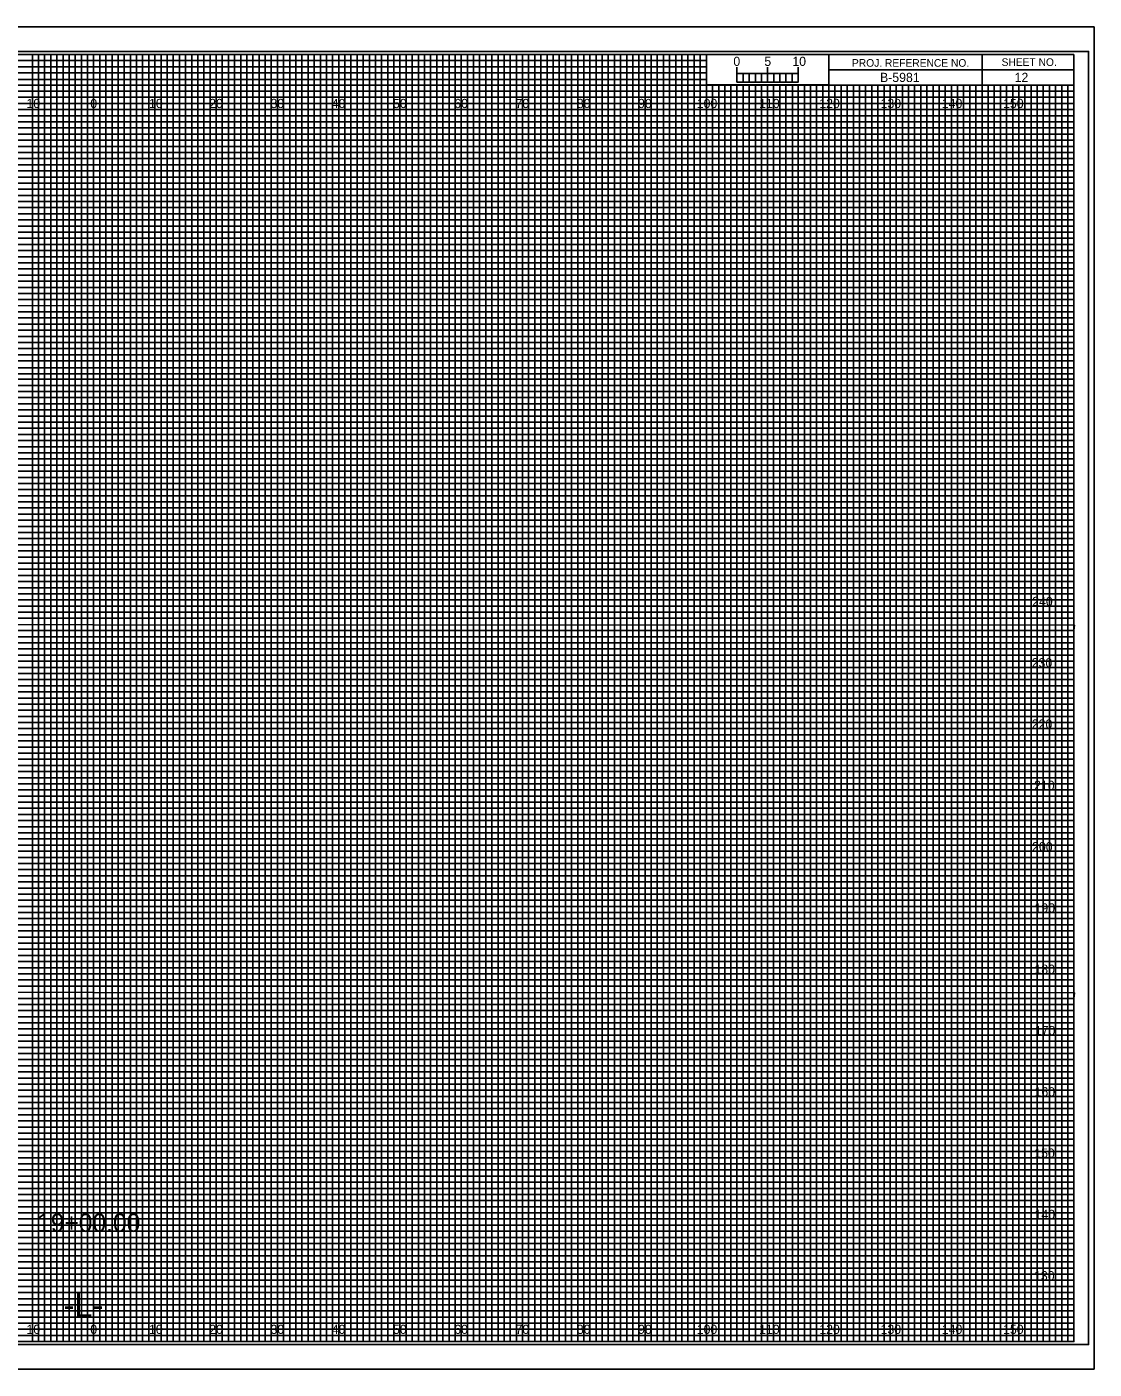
# Model space of a CAD drawing. Extents: x -13 to 323, y -5 to 4174.
# Drawn here: x 149.1 to 323.3, y 1315.5 to 1534.5 of the extents above; entities that cross this region are included whole.
import ezdxf

# ---------------------------------------------------------------- set-up
doc = ezdxf.new("R2010")
doc.units = 0
for name, color, linetype in [('Exist Cross Section Cell', 7, 'Continuous'), ('Exist XS Center Line Elevation Label', 7, 'Continuous'), ('Exist XS Ground Line', 7, 'Continuous'), ('Prop CMT Concrete Structures', 7, 'Continuous'), ('Prop CMT Guardrail Graphics', 7, 'Continuous'), ('Prop CMT Pvmt Course 1', 7, 'Continuous'), ('Prop CMT Pvmt Course 2', 7, 'Continuous'), ('Prop CMT Pvmt Course 3', 7, 'Continuous'), ('Prop CMT Pvmt Surface', 7, 'Continuous'), ('Prop CMT Shld Paved Course 1', 7, 'Continuous'), ('Prop CMT Shld Paved Course 2', 7, 'Continuous'), ('Prop CMT Shld Paved Course 3', 7, 'Continuous'), ('Prop CMT Subgrade Earthwork', 7, 'Continuous'), ('Prop XS Ditch Standard Text', 7, 'Continuous'), ('Prop XS SE Text', 7, 'Continuous'), ('Prop XS Side Slope Text', 7, 'Continuous'), ('Scratch_Level_0', 7, 'Continuous')]:
    doc.layers.add(name, color=color, linetype=linetype)

msp = doc.modelspace()

# ---------------------------------------------------------------- linework, layer by layer
at = {"layer": 'Exist XS Center Line Elevation Label'}
for points in [[(145, 1320), (155, 1320), (155, 1530), (165, 1530), (165, 1320), (175, 1320), (175, 1530), (185, 1530), (185, 1320), (195, 1320), (195, 1530), (205, 1530), (205, 1320), (215, 1320), (215, 1530), (225, 1530), (225, 1320), (235, 1320), (235, 1530), (245, 1530), (245, 1320), (255, 1320), (255, 1530), (259.93, 1530), (260, 1530), (260, 1525), (264.99, 1525), (264.99, 1320), (275, 1320), (275, 1525), (285, 1525), (285, 1320), (295, 1320), (295, 1525), (305, 1525), (305, 1320), (315, 1320), (315, 1525)], [(0, 1525), (275, 1525)], [(0, 1505), (320, 1505), (320, 1515), (0, 1515)], [(0, 1485), (320, 1485), (320, 1495), (0, 1495)], [(0, 1465), (320, 1465), (320, 1475), (0, 1475)], [(0, 1445), (320, 1445), (320, 1455), (0, 1455)], [(0, 1425), (320, 1425), (320, 1435), (0, 1435)], [(0, 1405), (320, 1405), (320, 1415), (0, 1415)], [(0, 1385), (320, 1385), (320, 1395), (0, 1395)], [(0, 1365), (320, 1365), (320, 1375), (0, 1375)], [(0, 1345), (320, 1345), (320, 1355), (0, 1355)], [(0, 1325), (320, 1325), (320, 1335), (0, 1335)]]:
    msp.add_lwpolyline(points, dxfattribs=at)
at = {"layer": 'Exist XS Ground Line'}
for p, q in [((150, 1530), (140, 1530)), ((150, 1320), (150, 1530)), ((170, 1530), (160, 1530)), ((160, 1530), (160, 1320)), ((170, 1320), (170, 1530)), ((190, 1530), (180, 1530)), ((180, 1530), (180, 1320)), ((190, 1320), (190, 1530)), ((210, 1530), (200, 1530)), ((200, 1530), (200, 1320)), ((210, 1320), (210, 1530)), ((230, 1530), (220, 1530)), ((220, 1530), (220, 1320)), ((230, 1320), (230, 1530)), ((250, 1530), (240, 1530)), ((240, 1530), (240, 1320)), ((250, 1320), (250, 1530)), ((260, 1530), (260, 1320)), ((270, 1320), (270, 1525)), ((290, 1525), (280, 1525)), ((280, 1525), (280, 1320)), ((290, 1320), (290, 1525)), ((310, 1525), (300, 1525)), ((300, 1525), (300, 1320)), ((310, 1320), (310, 1525)), ((160, 1320), (150, 1320)), ((180, 1320), (170, 1320)), ((200, 1320), (190, 1320)), ((220, 1320), (210, 1320)), ((240, 1320), (230, 1320)), ((260, 1320), (250, 1320)), ((280, 1320), (270, 1320)), ((300, 1320), (290, 1320)), ((320, 1320), (310, 1320)), ((320, 1320), (320, 1320))]:
    msp.add_line(p, q, dxfattribs=at)
for points in [[(0, 1520), (320, 1520), (320, 1510), (0, 1510)], [(0, 1500), (320, 1500), (320, 1490), (0, 1490)], [(0, 1480), (320, 1480), (320, 1470), (0, 1470)], [(0, 1460), (320, 1460), (320, 1450), (0, 1450)], [(0, 1440), (320, 1440), (320, 1430), (0, 1430)], [(0, 1420), (320, 1420), (320, 1410), (0, 1410)], [(0, 1400), (320, 1400), (320, 1390), (0, 1390)], [(0, 1380), (320, 1380), (320, 1370), (0, 1370)], [(0, 1360), (320, 1360), (320, 1350), (0, 1350)], [(0, 1340), (320, 1340), (320, 1330), (0, 1330)]]:
    msp.add_lwpolyline(points, dxfattribs=at)
at = {"layer": 'Prop CMT Pvmt Course 1'}
for p, q in [((323.3, 1534.5), (-13.4, 1534.5)), ((-13.4, 1315.5), (323.3, 1315.5))]:
    msp.add_line(p, q, dxfattribs=at)
at = {"layer": 'Prop CMT Pvmt Course 2'}
msp.add_lwpolyline([(-13.4, 1315.5), (323.3, 1315.5), (323.3, 1534.5), (-13.4, 1534.5)], close=True, dxfattribs=at)
at = {"layer": 'Prop CMT Pvmt Course 3'}
msp.add_lwpolyline([(-10.8, 1319.5), (322.4, 1319.5), (322.4, 1530.5), (-10.8, 1530.5)], close=True, dxfattribs=at)
at = {"layer": 'Prop CMT Shld Paved Course 1'}
for p, q in [((305, 1530), (305, 1525)), ((305, 1525), (305, 1530)), ((280, 1527.5), (280, 1525)), ((320, 1527.49), (280, 1527.49)), ((280, 1525), (320, 1525))]:
    msp.add_line(p, q, dxfattribs=at)
for points in [[(320, 1530), (0, 1530), (0, 1320), (320, 1320)], [(280, 1530), (260, 1530), (260, 1525.03), (280, 1525.03)], [(320, 1530), (280, 1530), (280, 1525), (320, 1525)]]:
    msp.add_lwpolyline(points, close=True, dxfattribs=at)
at = {"layer": 'Prop CMT Shld Paved Course 2'}
for p, q in [((267, 1525), (266.01, 1525)), ((266.01, 1525), (266.01, 1320)), ((267, 1320), (267, 1525)), ((269, 1525), (268, 1525)), ((268, 1525), (268, 1320)), ((269, 1320), (269, 1525)), ((266.01, 1320), (265, 1320)), ((268, 1320), (267, 1320))]:
    msp.add_line(p, q, dxfattribs=at)
for points in [[(150, 1320), (151, 1320), (151, 1530), (152, 1530), (152, 1320)], [(152, 1320), (153, 1320), (153, 1530), (154, 1530), (154, 1320)], [(155, 1320), (156, 1320), (156, 1530), (157, 1530), (157, 1320)], [(157, 1320), (158, 1320), (158, 1530), (159, 1530), (159, 1320)], [(160, 1320), (161, 1320), (161, 1530), (162, 1530), (162, 1320)], [(162, 1320), (163, 1320), (163, 1530), (164, 1530), (164, 1320)], [(165, 1320), (166, 1320), (166, 1530), (167, 1530), (167, 1320)], [(167, 1320), (168, 1320), (168, 1530), (169, 1530), (169, 1320)], [(170, 1320), (171, 1320), (171, 1530), (172, 1530), (172, 1320)], [(172, 1320), (173, 1320), (173, 1530), (174, 1530), (174, 1320)], [(175, 1320), (176, 1320), (176, 1530), (177, 1530), (177, 1320)], [(177, 1320), (178, 1320), (178, 1530), (179, 1530), (179, 1320)], [(180, 1320), (181, 1320), (181, 1530), (182, 1530), (182, 1320)], [(182, 1320), (183, 1320), (183, 1530), (184, 1530), (184, 1320)], [(185, 1320), (186, 1320), (186, 1530), (187, 1530), (187, 1320)], [(187, 1320), (188, 1320), (188, 1530), (189, 1530), (189, 1320)], [(190, 1320), (191, 1320), (191, 1530), (192, 1530), (192, 1320)], [(192, 1320), (193, 1320), (193, 1530), (194, 1530), (194, 1320)], [(195, 1320), (196, 1320), (196, 1530), (197, 1530), (197, 1320)], [(197, 1320), (198, 1320), (198, 1530), (199, 1530), (199, 1320)], [(200, 1320), (201, 1320), (201, 1530), (202, 1530), (202, 1320)], [(202, 1320), (203, 1320), (203, 1530), (204, 1530), (204, 1320)], [(205, 1320), (206, 1320), (206, 1530), (207, 1530), (207, 1320)], [(207, 1320), (208, 1320), (208, 1530), (209, 1530), (209, 1320)], [(210, 1320), (211, 1320), (211, 1530), (212, 1530), (212, 1320)], [(212, 1320), (213, 1320), (213, 1530), (214, 1530), (214, 1320)], [(215, 1320), (216, 1320), (216, 1530), (217, 1530), (217, 1320)], [(217, 1320), (218, 1320), (218, 1530), (219, 1530), (219, 1320)], [(220, 1320), (221, 1320), (221, 1530), (222, 1530), (222, 1320)], [(222, 1320), (223, 1320), (223, 1530), (224, 1530), (224, 1320)], [(225, 1320), (226, 1320), (226, 1530), (227, 1530), (227, 1320)], [(227, 1320), (228, 1320), (228, 1530), (229, 1530), (229, 1320)], [(230, 1320), (231, 1320), (231, 1530), (232, 1530), (232, 1320)], [(232, 1320), (233, 1320), (233, 1530), (234, 1530), (234, 1320)], [(235, 1320), (236, 1320), (236, 1530), (237, 1530), (237, 1320)], [(237, 1320), (238, 1320), (238, 1530), (239, 1530), (239, 1320)], [(240, 1320), (241, 1320), (241, 1530), (242, 1530), (242, 1320)], [(242, 1320), (243, 1320), (243, 1530), (244, 1530), (244, 1320)], [(245, 1320), (246, 1320), (246, 1530), (247, 1530), (247, 1320)], [(247, 1320), (248, 1320), (248, 1530), (249, 1530), (249, 1320)], [(250, 1320), (251, 1320), (251, 1530), (252, 1530), (252, 1320)], [(252, 1320), (253, 1320), (253, 1530), (254, 1530), (254, 1320)], [(255, 1320), (256, 1320), (256, 1530), (257, 1530), (257, 1320)], [(257, 1320), (258, 1320), (258, 1530), (259, 1530), (259, 1320)], [(260, 1320), (261, 1320), (261, 1525), (262.02, 1525), (262.02, 1320)], [(262, 1320), (263, 1320), (263, 1525), (263.99, 1525), (263.99, 1320)], [(270, 1320), (270.98, 1320), (270.98, 1525), (272, 1525), (272, 1320)], [(272, 1320), (273, 1320), (273, 1525), (274.05, 1525), (274.05, 1320)], [(275, 1320), (276, 1320), (276, 1525), (277, 1525), (277, 1320)], [(277, 1320), (278, 1320), (278, 1525), (279, 1525), (279, 1320)], [(280, 1320), (281, 1320), (281, 1525), (282, 1525), (282, 1320)], [(282, 1320), (283, 1320), (283, 1525), (284, 1525), (284, 1320)], [(285, 1320), (286, 1320), (286, 1525), (287, 1525), (287, 1320)], [(287, 1320), (288, 1320), (288, 1525), (289, 1525), (289, 1320)], [(290, 1320), (291, 1320), (291, 1525), (292, 1525), (292, 1320)], [(292, 1320), (293, 1320), (293, 1525), (294, 1525), (294, 1320)], [(295, 1320), (296, 1320), (296, 1525), (297, 1525), (297, 1320)], [(297, 1320), (298, 1320), (298, 1525), (299, 1525), (299, 1320)], [(300, 1320), (301, 1320), (301, 1525), (302, 1525), (302, 1320)], [(302, 1320), (303, 1320), (303, 1525), (304, 1525), (304, 1320)], [(305, 1320), (306, 1320), (306, 1525), (307, 1525), (307, 1320)], [(307, 1320), (308, 1320), (308, 1525), (309, 1525), (309, 1320)], [(310, 1320), (311, 1320), (311, 1525), (312, 1525), (312, 1320)], [(312, 1320), (313, 1320), (313, 1525), (314, 1525), (314, 1320)], [(315, 1320), (316, 1320), (316, 1525), (317, 1525), (317, 1320)], [(317, 1320), (318, 1320), (318, 1525), (319, 1525), (319, 1320)]]:
    msp.add_lwpolyline(points, dxfattribs=at)
at = {"layer": 'Prop CMT Shld Paved Course 3'}
for p, q in [((265, 1525.49), (265, 1527.9)), ((265, 1526.9), (265, 1527.9)), ((270, 1525.49), (270, 1527.9)), ((275, 1525.49), (275, 1527.9)), ((275, 1526.9), (275, 1527.9))]:
    msp.add_line(p, q, dxfattribs=at)
for points in [[(275, 1526.9), (265, 1526.9), (265, 1525.49), (275, 1525.49)], [(265, 1526.9), (266, 1526.9), (266, 1525.49), (265, 1525.49)], [(267, 1526.9), (268, 1526.9), (268, 1525.49), (267, 1525.49)], [(269, 1526.9), (270, 1526.9), (270, 1525.49), (269, 1525.49)], [(271, 1526.9), (272, 1526.9), (272, 1525.49), (271, 1525.49)], [(273, 1526.9), (274, 1526.9), (274, 1525.49), (273, 1525.49)]]:
    msp.add_lwpolyline(points, close=True, dxfattribs=at)
at = {"layer": 'Prop CMT Subgrade Earthwork'}
for p, q in [((150, 1320), (150, 1530)), ((160, 1320), (160, 1530)), ((170, 1320), (170, 1530)), ((180, 1320), (180, 1530)), ((190, 1320), (190, 1530)), ((200, 1320), (200, 1530)), ((210, 1320), (210, 1530)), ((220, 1320), (220, 1530)), ((230, 1320), (230, 1530)), ((240, 1320), (240, 1530)), ((250, 1320), (250, 1530)), ((260, 1320), (260, 1524.69)), ((270, 1320), (270, 1524.69)), ((280, 1320), (280, 1524.69)), ((290, 1320), (290, 1524.69)), ((300, 1320), (300, 1524.69)), ((310, 1320), (310, 1524.69)), ((0, 1520), (320, 1520)), ((0, 1510), (320, 1510)), ((0, 1500), (320, 1500)), ((0, 1490), (320, 1490)), ((0, 1480), (320, 1480)), ((0, 1470), (320, 1470)), ((0, 1460), (320, 1460)), ((0, 1450), (320, 1450)), ((0, 1440), (320, 1440)), ((0, 1430), (320, 1430)), ((0, 1420), (320, 1420)), ((0, 1410), (320, 1410)), ((0, 1400), (320, 1400)), ((0, 1390), (320, 1390)), ((0, 1380), (320, 1380)), ((0, 1370), (320, 1370)), ((0, 1360), (320, 1360)), ((0, 1350), (320, 1350)), ((0, 1340), (320, 1340)), ((0, 1330), (320, 1330))]:
    msp.add_line(p, q, dxfattribs=at)
at = {"layer": 'Scratch_Level_0'}
for p, q in [((0, 1529), (260, 1529)), ((260, 1529), (260, 1527.98)), ((260, 1527.98), (0, 1527.98)), ((0, 1527), (260, 1527)), ((260, 1527), (260, 1525.89)), ((260, 1525.89), (0, 1525.89)), ((0, 1524), (320, 1524))]:
    msp.add_line(p, q, dxfattribs=at)
for points in [[(0, 1523), (270, 1523), (320, 1523), (320, 1522), (0, 1522)], [(0, 1521), (320, 1521), (320, 1519), (0, 1519)], [(0, 1518), (320, 1518), (320, 1517), (0, 1516.98)], [(0, 1516), (320, 1516), (320, 1514), (0, 1514)], [(0, 1513), (320, 1513), (320, 1512), (0, 1512)], [(0, 1511), (320, 1511), (320, 1509), (0, 1509)], [(0, 1508), (320, 1508), (320, 1507), (0, 1507)], [(0, 1506), (320, 1506), (320, 1504), (0, 1504)], [(0, 1503), (320, 1503), (320, 1502), (0, 1502)], [(0, 1501), (320, 1501), (320, 1499), (0, 1499)], [(0, 1498), (320, 1498), (320, 1497), (0, 1497)], [(0, 1496), (320, 1496), (320, 1493.95), (320, 1493), (320, 1492), (0, 1492)], [(0, 1494), (320, 1494), (320, 1493), (0, 1493)], [(0, 1491), (320, 1491), (320, 1489), (0, 1489.03)], [(0, 1489.03), (320, 1489), (320, 1488), (0, 1488)], [(0, 1487), (320, 1487), (320, 1486), (0, 1486)], [(0, 1484), (320, 1484), (320, 1483), (0, 1483)], [(0, 1482), (320, 1482), (320, 1481), (0, 1481)], [(-0.07, 1478.89), (320, 1478.89), (320, 1477.88), (-0.07, 1477.88)], [(0, 1477), (320, 1477), (320, 1476), (0, 1476)], [(0, 1474), (320, 1474), (320, 1473), (0, 1473)], [(0, 1472), (320, 1472), (320, 1471), (0, 1471)], [(0, 1469), (320, 1469), (320, 1468), (0, 1468)], [(0, 1467), (320, 1467), (320, 1466), (0, 1466)], [(0, 1464), (320, 1464), (320, 1463), (0, 1463)], [(0, 1462), (320, 1462), (320, 1461), (0, 1461)], [(0, 1459), (320, 1459), (319.99, 1457.98), (0, 1458)], [(0, 1457), (320, 1457), (320, 1456), (0, 1456)], [(0, 1454), (320, 1454), (320, 1453), (0, 1453)], [(0, 1452), (320, 1452), (320, 1451), (0, 1451)], [(0, 1449), (320, 1449), (320, 1448), (0, 1448)], [(0, 1447), (320, 1447), (320, 1446), (0, 1446)], [(0, 1444), (320, 1444), (320, 1443), (0, 1443)], [(0, 1442), (320, 1442), (320, 1441), (0, 1441)], [(0, 1439), (320, 1439), (320, 1438), (0, 1438)], [(0, 1436.99), (320.07, 1436.91), (320, 1436), (0, 1436)], [(0, 1434), (320, 1434), (320, 1433), (0, 1433)], [(0, 1432), (320, 1432), (320, 1431), (0, 1431)], [(0, 1429), (320, 1429), (320, 1428), (0, 1428)], [(0, 1427), (320, 1427), (320, 1426), (0, 1426)], [(0, 1424), (320, 1424), (320, 1423), (0, 1423)], [(0, 1422), (320, 1422), (320, 1421), (0, 1421)], [(0, 1419), (320, 1419), (320, 1418), (0, 1418)], [(0, 1417), (320, 1417), (320, 1416), (0, 1416)], [(0, 1414), (320, 1414), (320, 1413), (0, 1413)], [(0, 1412), (320, 1412), (320, 1411), (0, 1411)], [(0, 1409), (320, 1409), (320, 1408), (0, 1408)], [(0, 1407), (320, 1407), (320, 1406), (0, 1406)], [(0, 1404), (320, 1404), (320, 1403), (0, 1403)], [(0, 1402), (320, 1402), (320, 1401), (0, 1401)], [(0, 1399), (320, 1399), (319.99, 1397.98), (0, 1398)], [(0, 1397), (320, 1397), (320, 1396), (0, 1396)], [(0, 1394), (320, 1394), (320, 1393), (0, 1393)], [(0, 1392), (320, 1392), (320, 1391), (0, 1391)], [(0, 1389), (320, 1389), (320, 1388), (0, 1388)], [(0, 1387), (320, 1387), (320, 1386), (0, 1386)], [(0, 1384), (320, 1384), (320, 1383), (0, 1383)], [(0, 1382), (320, 1382), (320, 1381), (0, 1381)], [(0, 1379), (320, 1379), (320, 1378), (0, 1378)], [(0, 1376.99), (320.07, 1376.91), (320, 1376), (0, 1376)], [(0, 1374), (320, 1374), (320, 1373), (0, 1373)], [(0, 1372), (320, 1372), (320, 1371), (0, 1371)], [(0, 1369), (320, 1369), (320, 1368), (0, 1368)], [(0, 1367), (320, 1367), (320, 1366), (0, 1366)], [(0, 1364), (320, 1364), (320, 1363), (0, 1363)], [(0, 1362), (320, 1362), (320, 1361), (0, 1361)], [(0, 1359), (320, 1359), (320, 1358), (0, 1358)], [(0, 1357), (320, 1357), (320, 1356), (0, 1356)], [(0, 1354), (320, 1354), (320, 1353), (0, 1353)], [(0, 1352), (320, 1352), (320, 1351), (0, 1351)], [(0, 1349), (320, 1349), (320, 1348), (0, 1348)], [(0, 1347), (320, 1347), (320, 1346), (0, 1346)], [(0, 1344), (320, 1344), (320, 1343), (0, 1343)], [(0, 1342), (320, 1342), (320, 1341), (0, 1341)], [(0, 1339), (320, 1339), (320, 1338), (0, 1338)], [(0, 1337), (320, 1337), (320, 1336), (0, 1336)], [(0, 1334), (320, 1334), (320, 1333), (0, 1333)], [(0, 1332), (320, 1332), (320, 1331), (0, 1331)], [(0, 1329), (320, 1329), (320, 1328), (0, 1328)], [(0, 1327), (320, 1327), (320, 1326), (0, 1326)], [(0, 1324), (320, 1324), (320, 1323), (0, 1323)], [(0, 1322), (320, 1322), (320, 1321), (0, 1321)]]:
    msp.add_lwpolyline(points, dxfattribs=at)

# ---------------------------------------------------------------- texts
at = {"layer": 'Exist Cross Section Cell'}
for s, p in [('10', (149.04, 1521.25)), ('0', (159.45, 1521.25)), ('0', (159.45, 1521.25)), ('10', (169.04, 1521.25)), ('20', (178.86, 1521.25)), ('30', (188.86, 1521.25)), ('40', (198.86, 1521.25)), ('50', (208.86, 1521.25)), ('60', (218.86, 1521.25)), ('70', (228.86, 1521.25)), ('80', (238.86, 1521.25)), ('90', (248.86, 1521.25)), ('100', (258.44, 1521.25)), ('110', (268.62, 1521.25)), ('120', (278.44, 1521.25)), ('130', (288.44, 1521.25)), ('140', (298.44, 1521.25)), ('150', (308.44, 1521.25)), ('10', (149.04, 1321.25)), ('0', (159.45, 1321.25)), ('0', (159.45, 1321.25)), ('10', (169.04, 1321.25)), ('20', (178.86, 1321.25)), ('30', (188.86, 1321.25)), ('40', (198.86, 1321.25)), ('50', (208.86, 1321.25)), ('60', (218.86, 1321.25)), ('70', (228.86, 1321.25)), ('80', (238.86, 1321.25)), ('90', (248.86, 1321.25)), ('100', (258.44, 1321.25)), ('110', (268.62, 1321.25)), ('120', (278.44, 1321.25)), ('130', (288.44, 1321.25)), ('140', (298.44, 1321.25)), ('150', (308.44, 1321.25))]:
    msp.add_text(s, height=1.5, dxfattribs=at).set_placement(p)
at = {"layer": 'Prop CMT Concrete Structures'}
msp.add_text('19+00.00', height=3, dxfattribs=at).set_placement((150.77, 1337.89))
at = {"layer": 'Prop CMT Guardrail Graphics'}
for s, p in [('240', (313.19, 1440)), ('230', (313.11, 1430)), ('220', (313.12, 1420)), ('210', (313.5, 1410)), ('200', (313.17, 1400)), ('190', (313.57, 1390)), ('180', (313.55, 1380)), ('170', (313.61, 1370)), ('160', (313.57, 1360)), ('150', (313.52, 1350)), ('140', (313.57, 1340)), ('130', (313.49, 1330))]:
    msp.add_text(s, height=1.5, dxfattribs=at).set_placement(p)
at = {"layer": 'Prop CMT Pvmt Surface'}
for s, p in [('5', (269.47, 1528.12)), ('10', (274.04, 1528.12))]:
    msp.add_text(s, height=1.5, dxfattribs=at).set_placement(p)
at = {"layer": 'Prop CMT Shld Paved Course 1'}
for s, p in [('PROJ. REFERENCE NO.', (283.77, 1527.99)), ('SHEET NO.', (308.19, 1528.12))]:
    msp.add_text(s, height=1.25, dxfattribs=at).set_placement(p)
at = {"layer": 'Prop CMT Shld Paved Course 3'}
msp.add_text('0', height=1.5, dxfattribs=at).set_placement((264.41, 1528.12))
at = {"layer": 'Prop XS Ditch Standard Text'}
msp.add_text('-L-', height=4, dxfattribs=at).set_placement((155.06, 1324))
at = {"layer": 'Prop XS SE Text'}
msp.add_text(' B-5981', height=1.5, dxfattribs=at).set_placement((287.79, 1525.5))
at = {"layer": 'Prop XS Side Slope Text'}
msp.add_text('12', height=1.5, dxfattribs=at).set_placement((310.32, 1525.5))

doc.saveas('drawing.dxf')
